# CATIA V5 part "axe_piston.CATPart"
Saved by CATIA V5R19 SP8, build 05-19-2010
Part number: axe_piston
Bounding box of the stored display mesh (mm): x 0 to 150, y -5 to 5, z -5 to 5
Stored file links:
  U:\Thinkmotion\Assemblage final\axe_piston.CATPart
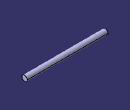
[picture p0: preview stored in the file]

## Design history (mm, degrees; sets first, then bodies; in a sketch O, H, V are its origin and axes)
Body1 (main body)
  Sketch1 on yz-plane, origin (0, 0, 0), H (0, 1, 0), V (0, 0, 1)
    circle A1 centre (0, 0) radius 5
  Pad1: profile Sketch1, direction (1, 0, 0), length 150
